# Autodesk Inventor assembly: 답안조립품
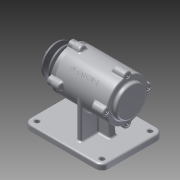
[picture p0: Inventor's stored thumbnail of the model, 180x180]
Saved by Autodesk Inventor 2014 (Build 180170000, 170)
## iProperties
Created: 2015-12
Part Number: 답안조립품
Document SubType Name: Assembly
Designer: test_03
Author: test_03
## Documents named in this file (11)
- C:\Users\test_03\Desktop\451207V1024\답안조립품.iam
- C:\Users\test_03\Desktop\451207V1024\V-벨트풀리.ipt
- C:\Users\test_03\Desktop\451207V1024\너트 M12x1.25.ipt
- C:\Users\test_03\Desktop\451207V1024\베어링 6204.ipt
- C:\Users\test_03\Desktop\451207V1024\본체.ipt
- C:\Users\test_03\Desktop\451207V1024\볼트 M4 x 12.ipt
- C:\Users\test_03\Desktop\451207V1024\오일실.ipt
- C:\Users\test_03\Desktop\451207V1024\축.ipt
- C:\Users\test_03\Desktop\451207V1024\커버.ipt
- C:\Users\test_03\Desktop\451207V1024\커버2.ipt
- C:\Users\test_03\Desktop\451207V1024\키(4 x 4 x 12).ipt
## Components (6 placed, 5 different names)
1. V-벨트풀리:1
2. KS B 1012 클래스 1 일반 - 미터 M12x1.25:1 — 각도:1, 각도:2
3. KS B 2023 6204 - 20 x 47 x 14:1
4. KS B 2804 D D - 20 32 8:1
5. KS B 1311 (I) 4 x 4 x 12:1
6. KS B 2023 6204 - 20 x 47 x 14:2
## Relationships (2: Angle 2)
- 각도:1 [Angle]: KS B 1012 클래스 1 일반 - 미터 M12x1.25:1
- 각도:2 [Angle]: KS B 1012 클래스 1 일반 - 미터 M12x1.25:1
